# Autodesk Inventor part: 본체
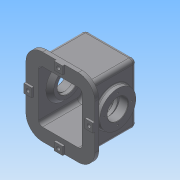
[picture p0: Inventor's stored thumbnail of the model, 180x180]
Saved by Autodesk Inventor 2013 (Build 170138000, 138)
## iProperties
Created: 2014-11
Part Number: 본체
Material: Generic
Document SubType Name: Modeling
Designer: Administrator
Density: 1 g/cm^3
Author: Administrator
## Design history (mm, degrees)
sketch "Sketch1"
  geometry: L1 (-65, 64)-(65, 64); L2 (65, 64)-(65, -64); L3 (65, -64)-(-65, -64); L4 (-65, -64)-(-65, 64); L5 (-65, 64)-(65, -64); L6 (65, 64)-(-65, -64); 1 further point
  constraints: 12 end point, 2 midpoint, 2 parallel, 1 horizontal, 1 perpendicular
  dimensions: "d0" = 130 distance of L2.end L3.end; "d2" = 128 distance of L1.end L2.end
extrude "Extrusion1" new body sketch "Sketch1" stored distance "d3" = 152; taper "d4" = 0 deg
sketch "Sketch3"
  geometry: L1 (-22, -174)-(152, -174); L2 (152, -174)-(152, 22); L3 (152, 22)-(-22, 22); L4 (-22, 22)-(-22, -174); L5 (-22, -174)-(152, 22); L6 (152, -174)-(-22, 22); 1 further point
  constraints: 12 end point, 2 midpoint, 2 parallel, 1 horizontal, 1 perpendicular
  dimensions: "d8" = 196 distance of L1.end L2.end; "d10" = 174 distance of L2.end L3.end
extrude "Extrusion2" join sketch "Sketch3" distance "d11" = 10; taper "d12" = 0 deg
sketch "Sketch4"
  geometry: L1 (0, 0)-(174, 0) reference; L2 (174, 0)-(174, 196) reference; L3 (174, 196)-(0, 196) reference; L4 (0, 196)-(0, 0) reference; L5 (76, 196)-(98, 196); L6 (98, 196)-(98, 176); L7 (98, 176)-(76, 176); L8 (76, 176)-(76, 196); L9 (154, 109)-(174, 109); L10 (174, 109)-(174, 87); L11 (174, 87)-(154, 87); L12 (154, 87)-(154, 109); L13 (76, 20)-(98, 20); L14 (98, 20)-(98, 0); L15 (98, 0)-(76, 0); L16 (76, 0)-(76, 20); L17 (0, 109)-(20, 109); L18 (20, 109)-(20, 87); L19 (20, 87)-(0, 87); L20 (0, 87)-(0, 109); 5 further points
  constraints: 32 end point, 8 parallel, 7 midpoint, 4 horizontal, 4 perpendicular, 1 collinear, 1 vertical alignment
  dimensions: "d13" = 22 distance of L6.end L7.end; "d16" = 20 distance of L5.end L6.end; "d17" = 22 distance of L11.end L9.start; "d18" = 20 distance of L10.end L11.end; "d19" = 22 distance of L13.start L13.end; "d20" = 20 distance of L13.end L14.end; "d21" = 22 distance of L17.end L18.end; "d22" = 20 distance of L17.start L17.end
extrude "Extrusion3" join sketch "Sketch4" distance "d23" = 5; taper "d24" = 0 deg
sketch "Sketch11"
  geometry: L1 (-22, -118)-(0, -118) reference; L2 (0, -118)-(152, -118) reference; L3 (152, -118)-(174, -118) reference; L4 (174, -118)-(174, -128) reference; L5 (174, -128)-(-22, -128) reference; L6 (-22, -128)-(-22, -118) reference; L7 (0, -118)-(0, 0) reference; L8 (0, 0)-(152, 0) reference; L9 (152, 0)-(152, -118) reference; L10 (76, -118)-(76, -60); C1 r 45.5 at (76, -60); 1 further point
  constraints: 2 end point, 1 centre point, 1 coincident, 1 midpoint, 1 parallel
  dimensions: "d40" = 58 distance of L10.start L10.end; "d41" = 91 diameter of C1
extrude "Extrusion5" join sketch "Sketch11" distance "d42" = 12; taper "d43" = 0 deg
mirror "Mirror1"
sketch "Sketch14"
  geometry: L1 (0, 0)-(84.121, -17.88); L2 (84.121, -17.88)-(90.566, 12.442); L3 (90.566, 12.442)-(64, 18.089); L4 (84.121, -17.88)-(77.675, -48.203); L5 (77.675, -48.203)-(64, -45.296); L6 (64, 76)-(-54, 76) reference; L7 (-54, -76)-(-54, -98) reference; L8 (-54, -98)-(-69, -98) reference; L9 (-69, -98)-(-69, -78) reference; L10 (-69, -78)-(-64, -78) reference; L11 (-64, -78)-(-64, 78) reference; L12 (-64, 78)-(-69, 78) reference; L13 (-69, 78)-(-69, 98) reference; L14 (-69, 98)-(-54, 98) reference; L15 (-54, 98)-(-54, 76) reference; L16 (-54, 76)-(64, 76) reference; L17 (64, 76)-(64, -76) reference; L18 (64, -76)-(-54, -76) reference
  constraints: 10 end point, 3 perpendicular, 2 point on line, 1 parallel
  dimensions: "d46" = 168 deg angle of L6 L1; "d47" = 31 distance between parallel lines of L3 L1; "d49" = 31 distance between parallel lines of L5 L1; "d50" = 86 distance from line of L1.start L4
extrude "Extrusion6" join sketch "Sketch14" stored distance "d51" = 62; taper "d52" = 0 deg
fillet "Fillet1" dims "d53" = 31
sketch "Sketch16"
  geometry: L1 (-54, -76)-(-54, -98) reference; L2 (-54, -98)-(-69, -98) reference; L3 (-69, -98)-(-69, -78) reference; L4 (-69, -78)-(-64, -78) reference; L5 (-64, -78)-(-64, 78) reference; L6 (-64, 78)-(-69, 78) reference; L7 (-69, 78)-(-69, 98) reference; L8 (-69, 98)-(-54, 98) reference; L9 (-54, 98)-(-54, 76) reference; L10 (-54, 76)-(64, 76) reference; L11 (64, 76)-(64, 18.089) reference; L12 (64, 18.089)-(90.566, 12.442) reference; L13 (90.566, 12.442)-(77.675, -48.203) reference; L14 (77.675, -48.203)-(64, -45.296) reference; L15 (64, -45.296)-(64, -76) reference; L16 (64, -76)-(-54, -76) reference; L17 (-54, -76)-(-54, -98) reference; L18 (-54, -98)-(-69, -98) reference; L19 (-69, -98)-(-69, -78) reference; L20 (-69, -78)-(-64, -78) reference; L21 (-64, -78)-(-64, 78) reference; L22 (-64, 78)-(-69, 78) reference; L23 (-69, 78)-(-69, 98) reference; L24 (-69, 98)-(-54, 98) reference; L25 (-54, 98)-(-54, 76) reference; L26 (-54, 76)-(64, 76) reference; L27 (64, 76)-(64, 18.089) reference; L28 (64, 18.089)-(90.566, 12.442) reference; L29 (90.566, 12.442)-(77.675, -48.203) reference; L30 (77.675, -48.203)-(64, -45.296) reference; L31 (64, -45.296)-(64, -76) reference; L32 (64, -76)-(-54, -76) reference; L33 (54, 46)-(54, -46); L34 (34, 66)-(-64, 66); L35 (34, -66)-(-64, -66); A1 r 20 centre (34, 46) between (54, 46) and (34, 66); A2 r 20 centre (34, -46) between (34, -66) and (54, -46); 1 further point
  constraints: 6 end point, 4 point on circle, 4 tangent, 2 centre point, 2 perpendicular, 2 point on line, 1 equal radius
  dimensions: "d55" = 20 radius of A1; "d56" = 10 distance between parallel lines of L34 L10; "d57" = 10 distance between parallel lines of L16 L35; "d58" = 10 distance between parallel lines of L11 L33
extrude "Extrusion7" cut sketch "Sketch16" stored distance "d59" = 110; taper "d60" = 0 deg
sketch "Sketch17"
  geometry: C1 r 45.5 at (0, 0) reference; C2 r 26 at (0, 0); 1 further point
  constraints: 1 centre point, 1 coincident
  dimensions: "d61" = 52 diameter of C2
extrude "Extrusion8" cut sketch "Sketch17" distance "d62" = 32; taper "d63" = 0 deg
sketch "Sketch18"
  geometry: C1 r 45.5 at (0, 0) reference; C2 r 26 at (0, 0); 1 further point
  constraints: 1 centre point, 1 coincident
  dimensions: "d64" = 52 diameter of C2
extrude "Extrusion9" cut sketch "Sketch18" distance "d65" = 32; taper "d66" = 0 deg
sketch "Sketch19"
  geometry: C1 r 26 at (0, 0) reference; 2 further points
  constraints: 1 vertical alignment
  dimensions: "d67" = 35 distance of point (0, 35) C1.centre
hole "Hole1" sketch "Sketch19" at (0, 35) diameter "d68" = 3.242; stored, may be unused: countersink angle "d72" = 90 deg, drill point angle "d74" = 118 deg; dims "d69" = 13, "d70" = 4, "d71" = 2, "d73" = 16
pattern_circular "Circular Pattern1" dims angle "d76" = 360 deg
mirror "Mirror2"
hole "Hole2" sketch "Sketch20" diameter "d79" = 9; stored, may be unused: countersink angle "d83" = 90 deg, drill point angle "d85" = 0 deg; dims "d80" = 13, "d81" = 14, "d82" = 8.6, "d84" = 15
mirror "Mirror3"
sketch "Sketch21"
  geometry: L1 (-22, -22)-(152, -22) reference; 2 further points
  constraints: 1 vertical alignment
  dimensions: "d89" = 10 distance from line of L1 point (65, -12)
hole "Hole3" sketch "Sketch21" at (65, -12) diameter "d90" = 9; stored, may be unused: countersink angle "d94" = 90 deg, drill point angle "d96" = 0 deg; dims "d91" = 13, "d92" = 14, "d93" = 8.6, "d95" = 15
mirror "Mirror4"
fillet "Fillet2" dims "d97" = 10
sketch "Sketch23"
  geometry: L1 (-84, -62.6)-(-81.5, -62.6) reference; L2 (-81.5, -62.6)-(-81.5, -69) reference; L3 (-81.5, -69)-(-87, -69) reference; L4 (-87, -69)-(-87, -54) reference; L5 (-87, -54)-(-84, -54) reference; L6 (-84, -54)-(-84, -62.6) reference; L7 (81.5, -62.6)-(84, -62.6) reference; L8 (84, -62.6)-(84, -54) reference; L9 (84, -54)-(87, -54) reference; L10 (87, -54)-(87, -69) reference; L11 (87, -69)-(81.5, -69) reference; L12 (81.5, -69)-(81.5, -62.6) reference; L13 (-55, 30)-(-77, 30) reference; L14 (-77, 30)-(-77, 37.379) reference; L15 (-77, 37.379)-(-61, 37.379) reference; L16 (-55, 54)-(-55, 30) reference; L17 (-77, -22)-(-55, -22) reference; L18 (-55, -22)-(-55, -64) reference; L19 (-61, -29.379)-(-77, -29.379) reference; L20 (-77, -29.379)-(-77, -22) reference; L21 (77, 30)-(55, 30) reference; L22 (55, 30)-(55, 54) reference; L23 (61, 37.379)-(77, 37.379) reference; L24 (77, 37.379)-(77, 30) reference; L25 (55, -22)-(77, -22) reference; L26 (77, -22)-(77, -29.379) reference; L27 (77, -29.379)-(61, -29.379) reference; L28 (55, -64)-(55, -22) reference; L29 (65, 49.5)-(77, 49.5) reference; L30 (77, 49.5)-(77, 40.621) reference; L31 (77, 40.621)-(61, 40.621) reference; L32 (55, 54)-(-55, 54) reference; L33 (-61, 40.621)-(-77, 40.621) reference; L34 (-77, 40.621)-(-77, 49.5) reference; L35 (-77, 49.5)-(-65, 49.5) reference; L36 (-55, 64)-(-27.999, 64) reference; L37 (-25.037, 87.921)-(25.037, 87.921) reference; L38 (27.999, 64)-(55, 64) reference; L39 (-67, -64)-(-67, -69) reference; L40 (-67, -69)-(-72.5, -69) reference; L41 (-72.5, -69)-(-72.5, -62.6) reference; L42 (-72.5, -62.6)-(-70, -62.6) reference; L43 (-70, -62.6)-(-70, -54) reference; L44 (-70, -54)-(-65, -54) reference; L45 (-65, -54)-(-65, -41.5) reference; L46 (-65, -41.5)-(-77, -41.5) reference; L47 (-77, -41.5)-(-77, -32.621) reference; L48 (-77, -32.621)-(-61, -32.621) reference; L49 (-55, -64)-(-67, -64) reference; L50 (67, -69)-(67, -64) reference; L51 (67, -64)-(55, -64) reference; L52 (61, -32.621)-(77, -32.621) reference; L53 (77, -32.621)-(77, -41.5) reference; L54 (77, -41.5)-(65, -41.5) reference; L55 (65, -41.5)-(65, -54) reference; L56 (65, -54)-(70, -54) reference; L57 (70, -54)-(70, -62.6) reference; L58 (70, -62.6)-(72.5, -62.6) reference; L59 (72.5, -62.6)-(72.5, -69) reference; L60 (72.5, -69)-(67, -69) reference; L61 (-55, 45.5)-(-45, 35.5); L62 (-45, 35.5)-(-45, 26); L63 (-45, 26)-(-55, 26); L64 (-55, 26)-(-55, 45.5)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; A1 r 10 centre (-55, 54) between (-55, 64) and (-65, 54) reference; A2 r 10 centre (55, 54) between (65, 54) and (55, 64) reference; 2 further points; 2 other entities
  constraints: 10 end point, 4 perpendicular, 1 point on line, 2 other
  dimensions: "d99" = 52 diameter of L63 L65; "d101" = 71 diameter of L61.end L65; "d102" = 91 diameter of L61.start L65; "d103" = 10 distance between parallel lines of L62 L16
revolve "Revolution1" sketch "Sketch23" stored, may be unused: angle "d104" = 90 deg
mirror "Mirror5"
hole "Hole4" diameter "d107" = 30; stored, may be unused: countersink angle "d111" = 90 deg, drill point angle "d113" = 0 deg; dims "d105" = 10, "d106" = 10, "d108" = 13, "d109" = 42, "d110" = 25, "d112" = 15
sketch "Sketch24"
  geometry: L1 (-55, 54)-(-55, -54) reference; L2 (-87, -54)-(-55, -54) reference; L3 (-87, -64)-(-87, -54) reference; L4 (87, -64)-(-87, -64) reference; L5 (87, -54)-(87, -64) reference; L6 (55, -54)-(87, -54) reference; L7 (-55, -54)-(55, -54) reference; L8 (55, 54)-(-55, 54) reference; L9 (55, -54)-(55, 54) reference; L10 (-55, 54)-(-55, -54) reference; L11 (-87, -54)-(-55, -54) reference; L12 (-87, -64)-(-87, -54) reference; L13 (87, -64)-(-87, -64) reference; L14 (87, -54)-(87, -64) reference; L15 (55, -54)-(87, -54) reference; L16 (-55, -54)-(55, -54) reference; L17 (55, 54)-(-55, 54) reference; L18 (55, -54)-(55, 54) reference; 2 further points
  constraints: 1 vertical alignment, 1 other
  dimensions: "d114" = 92 distance from line of L4 point (0, 28)
emboss "Emboss1" sketch "Sketch24" dims "d0" = 130, "d2" = 128, "d115" = 1, "d116" = 0
fillet "Fillet3" dims "d117" = 10
fillet "Fillet4" dims "d118" = 3
chamfer "Chamfer1" distance "d120" = 1; stored, may be unused: second distance "d121" = 2, angle "d122" = 45 deg
fillet "Fillet6" dims "d123" = 42
fillet "Fillet7" dims "d124" = 3
body "Solid1"
node "Project Cut Edges5"
node "Project Cut Edges8"
node "Project Cut Edges9"
node "Project Cut Edges10"
node "Project Cut Edges14"
node "Project Cut Edges15"
node "Project Cut Edges16"
other parameters: "d88" = 10
